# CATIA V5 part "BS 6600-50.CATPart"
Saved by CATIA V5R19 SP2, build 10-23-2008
Part number: BS 6600-50
Bounding box of the stored display mesh (mm): x -59.975 to 59.975, y -59.975 to 59.975, z 0 to 175
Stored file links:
  C:\Users\Bora\Desktop\3D Katı model\BS serisi\BS 6600\BS 6600-50.CATPart
  C:\Program Files\Dassault Systemes\B19\intel_a\reffiles\standard\MetricThickPitch.txt
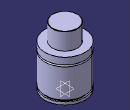
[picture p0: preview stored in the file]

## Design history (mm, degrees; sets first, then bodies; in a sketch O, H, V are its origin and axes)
Body1 (main body)
  Sketch1 on yz-plane, origin (0, 0, 0), H (0, 1, 0), V (0, 0, 1)
    point P1 (60, 104)
    point P2 (60, 99)
    point P3 (60, 104)
    point P7 (37.5, 174)
    point P9 (37.5, 174)
    point P14 (60, 99)
    arc A1 centre (60, 101.5) radius 2.5 from (60, 104) to (60, 99) ccw
    line L1 (60, 104) -> (60, 124)
    line L2 (60, 0) -> (60, 8)
    arc A2 centre (36.5, 174) radius 1 from (37.5, 174) to (36.5, 175) ccw
    line L3 (37.5, 174) -> (37.5, 124)
    line L4 (56, 13) -> (56, 8)
    line L5 (60, 13) -> (60, 99)
    line L6 (36.5, 175) -> (0, 175)
    point P15 (0, 175)
    line L7 (37.5, 124) -> (60, 124)
    line L8 (0, 0) -> (60, 0)
    line L9 (56, 13) -> (60, 13)
    line L10 (56, 8) -> (60, 8)
    coincidence: P15 V, P1 P3, P2 P14, P7 P9
    tangency: L6 A2
    horizontal: L7 H, L8 H, L9 H, L10 H
  Shaft1: profile Sketch1, axis Sketch1.V, angle 360
  Sketch2 on face of Shaft1 from Sketch1.L8, origin (0, 0, 0), H (1, 0, 0), V (0, -1, 0)
    point P1 (40, 0)
    distance V P1 = 40
  Hole1: placed by Sketch2, at (40, 0, 0) direction (0, 0, 1), diameter 8.376, depth 8, threaded "M10", thread diameter 10, thread depth 8, pitch 1.5
  CircPattern1: of Hole1, instances 4, angular step 90, axis from xy-plane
